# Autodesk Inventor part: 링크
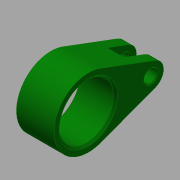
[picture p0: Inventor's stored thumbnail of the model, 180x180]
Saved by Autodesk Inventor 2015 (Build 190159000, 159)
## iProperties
Created: 2016-08
Part Number: 링크
Material: 강철, 탄소
Document SubType Name: Modeling
Designer: mduedu
Density: 7.87 g/cm^3
Appearance: 진녹색
Mass: 80.4021 g
Surface Area: 54.1946 cm^2
Volume: 10.2163 cm^3
Author: mduedu
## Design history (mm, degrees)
sketch "스케치1"
  geometry: L1 (32.1, 5.62)-(5.775, 15.456); L2 (32.1, -5.62)-(5.775, -15.456); C1 r 13 at (0, 0); C2 r 3 at (30, 0); A1 r 16.5 centre (0, 0) between (5.775, 15.456) and (5.775, -15.456); A2 r 6 centre (30, 0) between (32.1, 5.62) and (32.1, -5.62); 1 further point
  constraints: 4 centre point, 4 end point, 4 point on circle, 4 tangent, 3 coincident, 1 horizontal alignment
  dimensions: "d0" = 33 diameter of A1; "d2" = 12 diameter of A2; "d3" = 30 distance of A2.centre point (0, 0); "d4" = 26 diameter of C1; "d5" = 6 diameter of C2
extrude "돌출1" new body sketch "스케치1" stored distance "d6" = 18; taper "d7" = 0 deg
sketch "스케치2"
  geometry: L1 (-9, 36)-(9, 36) reference; L2 (0, 0)-(0, 36); L3 (-4, 36)-(4, 36); L4 (4, 36)-(4, 22); L5 (4, 22)-(-4, 22); L6 (-4, 22)-(-4, 36)
  constraints: 10 end point, 2 midpoint, 2 parallel, 1 horizontal, 1 perpendicular, 1 point on line
  dimensions: "d8" = 8 distance between parallel lines of L4 L6; "d10" = 14 distance of L3.end L4.end
extrude "돌출2" cut sketch "스케치2" stored distance "d11" = 20; taper "d12" = 0 deg
chamfer "모따기1" distance "d13" = 1; stored, may be unused: second distance "d14" = 2, angle "d15" = 45 deg
chamfer "모따기2" distance "d16" = 0.5; stored, may be unused: second distance "d17" = 2, angle "d18" = 45 deg
node "솔리드1"
